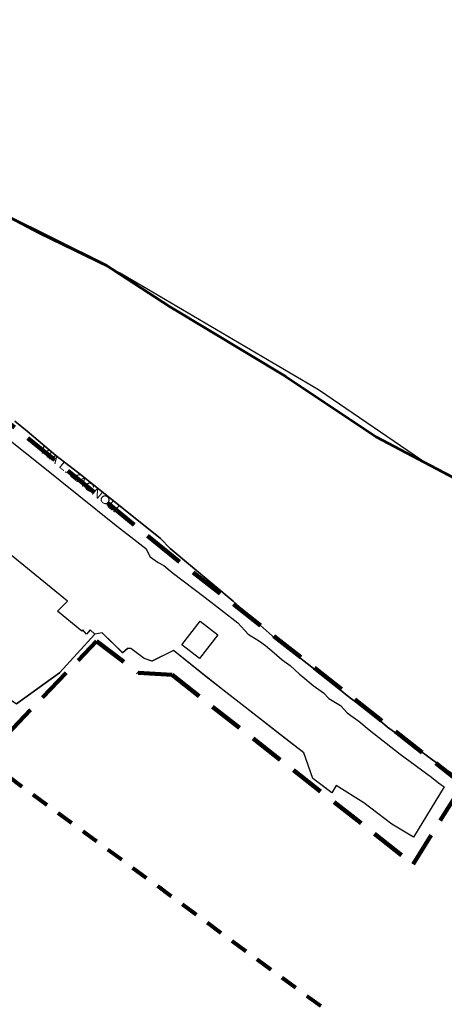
# Model space of a CAD drawing. Extents: x 654952 to 658955, y 890426 to 894481.
# Drawn here: x 657981 to 658129.5, y 893842.8 to 894187.9 of the extents above; entities that cross this region are included whole.
import ezdxf

# ---------------------------------------------------------------- set-up
doc = ezdxf.new("R2010")
doc.units = 0
doc.header["$LTSCALE"] = 4
doc.linetypes.add('MEDIUM_DASHED', pattern=[4.5, 3, -1.5])
doc.linetypes.add('SHORT_DASHED', pattern=[2.7, 1.5, -1.2])
for name, color, linetype, lineweight in [('11', 7, 'Continuous', 25), ('31', 7, 'Continuous', 25), ('41', 7, 'SHORT_DASHED', 80), ('43', 7, 'Continuous', 25), ('5', 7, 'Continuous', 25), ('59', 7, 'Continuous', 53), ('6', 7, 'Continuous', 25), ('7', 7, 'MEDIUM_DASHED', 100), ('9', 7, 'Continuous', 25)]:
    doc.layers.add(name, color=color, linetype=linetype, lineweight=lineweight)
doc.layers.add('58', color=7, linetype='Continuous')

msp = doc.modelspace()

# ---------------------------------------------------------------- linework, layer by layer
at = {"layer": '11'}
msp.add_lwpolyline([(657952.62, 893967.44), (657979.85, 893948.55), (657994.86, 893959.44), (658007.24, 893972.94), (658005.62, 893974.44), (658004.36, 893972.94), (658003.12, 893974.44), (658002.71, 893973.96), (657994.24, 893980.94), (657997.74, 893984.44), (657963.86, 894011.94), (657950.62, 894023.44), (657927.49, 894034.44), (657911.62, 894044.94), (657896.36, 894051.44), (657887.99, 894054.94), (657875.74, 894061.44), (657878.86, 894067.92), (657833.36, 894083.94), (657828.12, 894085.94), (657823.74, 894087.44)], dxfattribs=at)
at = {"layer": '31'}
msp.add_lwpolyline([(658129.47, 893919.47), (658118.76, 893901.94), (658111.13, 893906.44), (658101.39, 893913.94), (658091.63, 893919.94), (658090.14, 893917.44), (658086.82, 893919.94), (658083.51, 893922.44), (658080.38, 893931.44), (658059.88, 893947.44), (658053.07, 893952.69), (658046.26, 893957.94), (658034.75, 893967.15), (658027.26, 893963.44), (658024.51, 893964.44), (658019.89, 893967.94), (658018.76, 893967.94), (658017.01, 893966.44), (658009.88, 893973.44), (658007.25, 893972.94), (657994.88, 893959.44), (657979.87, 893948.55)], dxfattribs=at)
at = {"layer": '41'}
msp.add_line((658086.27, 893842.76), (657962.08, 893934.12), dxfattribs=at)
at = {"layer": '43'}
for points in [[(658266.41, 893937.09), (658214.83, 893967.25), (658194.33, 893989.87), (658168.89, 894009.06), (658121.55, 894033.74), (658121.55, 894033.74), (658085.51, 894058.42), (658016.08, 894099.23), (658016.08, 894099.23), (657987.82, 894112.94), (657939.76, 894138.3), (657874.04, 894162.29), (657811.4, 894192.37), (657779.35, 894208.91), (657757.45, 894224.67), (657703.03, 894250.03), (657703.03, 894250.03), (657646.5, 894254.15)], [(657979.26, 894047.44), (657983.63, 894043.94), (657993.63, 894035.44), (658002.76, 894028.44), (658030.26, 894006.44), (658033.63, 894002.94), (658055.63, 893984.44), (658070.38, 893971.44), (658086.88, 893958.44), (658096.26, 893950.94), (658104.38, 893944.94), (658109.63, 893940.44), (658118.19, 893934.19), (658126.76, 893927.94), (658135.26, 893921.94)]]:
    msp.add_lwpolyline(points, dxfattribs=at)
at = {"layer": '5'}
for points in [[(657970.24, 894046.44), (657989.24, 894031.44), (658014.12, 894011.44), (658025.12, 894002.94), (658026.62, 893999.94), (658029.36, 893997.94), (658031.36, 893996.94), (658034.36, 893994.44), (658045.8, 893985.69), (658057.24, 893976.94), (658060.86, 893972.94), (658064.86, 893970.44), (658066.99, 893968.94), (658069.99, 893966.44), (658072.74, 893963.94), (658075.62, 893961.94), (658078.86, 893958.94), (658079.99, 893957.94), (658083.62, 893954.94), (658087.24, 893952.44), (658089.12, 893950.44), (658093.12, 893947.94), (658095.49, 893945.44), (658097.62, 893943.94), (658099.62, 893942.44), (658103.24, 893939.44)], [(658135.26, 893921.94), (658126.76, 893927.94), (658118.19, 893934.19), (658109.63, 893940.44), (658104.38, 893944.94), (658096.26, 893950.94), (658086.88, 893958.44), (658070.38, 893971.44), (658055.63, 893984.44), (658033.63, 894002.94), (658030.26, 894006.44), (658002.76, 894028.44), (657993.63, 894035.44), (657983.63, 894043.94), (657979.26, 894047.44)], [(658103.24, 893939.44), (658113.99, 893930.94), (658124.99, 893922.94), (658127.49, 893920.94), (658129.45, 893919.47)]]:
    msp.add_lwpolyline(points, dxfattribs=at)
at = {"layer": '59'}
for points in [[(657431.84, 894352.05), (657500.4, 894338.39), (657554.69, 894302.38), (657602.47, 894274.44), (657631.94, 894262.63), (657689.95, 894257.67), (657735.24, 894235.94), (657762.24, 894219.79), (657775.57, 894210.48), (657838.55, 894179.75), (657855.92, 894171.05), (657890.67, 894158.95), (657926.03, 894145.91), (657975.36, 894119.83), (658011.03, 894102.14), (658033.37, 894087.55)], [(658033.37, 894087.55), (658074.01, 894063.03), (658105.65, 894041.92), (658154.04, 894016.47), (658177, 894000.01), (658196.24, 893978.59), (658267.28, 893936.06), (658288.06, 893908.75), (658400.68, 893840.75), (658358.49, 893763.16), (658343.9, 893727.46), (658322.5, 893619.12)]]:
    msp.add_lwpolyline(points, dxfattribs=at)
at = {"layer": '6'}
msp.add_lwpolyline([(658044.11, 893977.48), (658050.26, 893972.69), (658043.81, 893964.4), (658037.65, 893969.2)], close=True, dxfattribs=at)
at = {"layer": '7'}
msp.add_lwpolyline([(657976.52, 893937.75), (658007.85, 893970.48), (658022.47, 893959.34), (658034.3, 893958.65), (658118.53, 893892.48), (658135.93, 893920.34), (658035, 893999.74), (657925.71, 894088.89)], dxfattribs=at)
msp.add_lwpolyline([(657976.52, 893937.75), (658007.85, 893970.48), (658022.47, 893959.34), (658034.3, 893958.65), (658118.53, 893892.48), (658135.93, 893920.34), (658035, 893999.74), (657925.71, 894088.89)], dxfattribs=at)
at = {"layer": '9'}
for points in [[(657970.24, 894046.44), (657989.24, 894031.44), (658014.12, 894011.44), (658025.12, 894002.94), (658026.62, 893999.94), (658029.36, 893997.94), (658031.36, 893996.94), (658034.36, 893994.44), (658045.8, 893985.69), (658057.24, 893976.94), (658060.86, 893972.94), (658064.86, 893970.44), (658066.99, 893968.94), (658069.99, 893966.44), (658072.74, 893963.94), (658075.62, 893961.94), (658078.86, 893958.94), (658079.99, 893957.94), (658083.62, 893954.94), (658087.24, 893952.44), (658089.12, 893950.44), (658093.12, 893947.94), (658095.49, 893945.44), (658097.62, 893943.94), (658099.62, 893942.44), (658103.24, 893939.44)], [(658103.24, 893939.44), (658113.99, 893930.94), (658124.99, 893922.94), (658127.49, 893920.94), (658129.45, 893919.47), (658118.74, 893901.94), (658111.12, 893906.44), (658101.36, 893913.94), (658091.62, 893919.94), (658090.12, 893917.44), (658083.49, 893922.44), (658080.36, 893931.44), (658073.86, 893936.44), (658059.86, 893947.44), (658046.24, 893957.94), (658034.73, 893967.15), (658027.24, 893963.44), (658024.49, 893964.44), (658019.86, 893967.94), (658018.74, 893967.94), (658016.99, 893966.44), (658009.86, 893973.44), (658007.24, 893972.94), (658005.62, 893974.44), (658004.36, 893972.94), (658003.12, 893974.44), (658002.71, 893973.96), (657994.24, 893980.94), (657997.74, 893984.44), (657963.86, 894011.94)]]:
    msp.add_lwpolyline(points, dxfattribs=at)

# ---------------------------------------------------------------- texts
at = {"layer": '58', "width": 1.25}
msp.add_text('VIA L. ZAGNOLI', height=2.801, rotation=320.716, dxfattribs=at).set_placement((657987.61, 894037.12))

doc.saveas('drawing.dxf')
